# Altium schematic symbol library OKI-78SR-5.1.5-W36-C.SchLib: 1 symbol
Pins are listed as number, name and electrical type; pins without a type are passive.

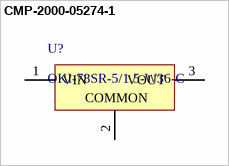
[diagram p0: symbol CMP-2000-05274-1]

## CMP-2000-05274-1
designator U?, comment OKI-78SR-5/1.5-W36-C
Non-Isolated DC/DC Converter, 7.5 W, 7 to 36 V, 1.5 A, -40 to 85 degC, 3-Pin THD, RoHS; Manufacturer: Murata; Current - Output (Max): 1.5A; Power (Watts) - Max: 8W; Efficiency: 90.5%; Voltage - Input (Min): 7V; Voltage - Input (Max): 36V; Voltage - Output 1: 5V; Number of Outputs: 1
footprint MURA-OKI-78SR-3 (THMT, 3-Leads, Body 10.4x7.6mm)
pins: 1 VIN (power), 2 COMMON (power), 3 VOUT (power)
